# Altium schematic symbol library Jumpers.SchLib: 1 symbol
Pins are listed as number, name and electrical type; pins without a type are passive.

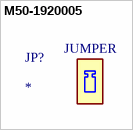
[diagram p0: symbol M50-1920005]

## M50-1920005
designator JP?
Link (Jumper); Manufacturer_Name: Harwin; Manufacturer_Part_Number: M50-1920005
